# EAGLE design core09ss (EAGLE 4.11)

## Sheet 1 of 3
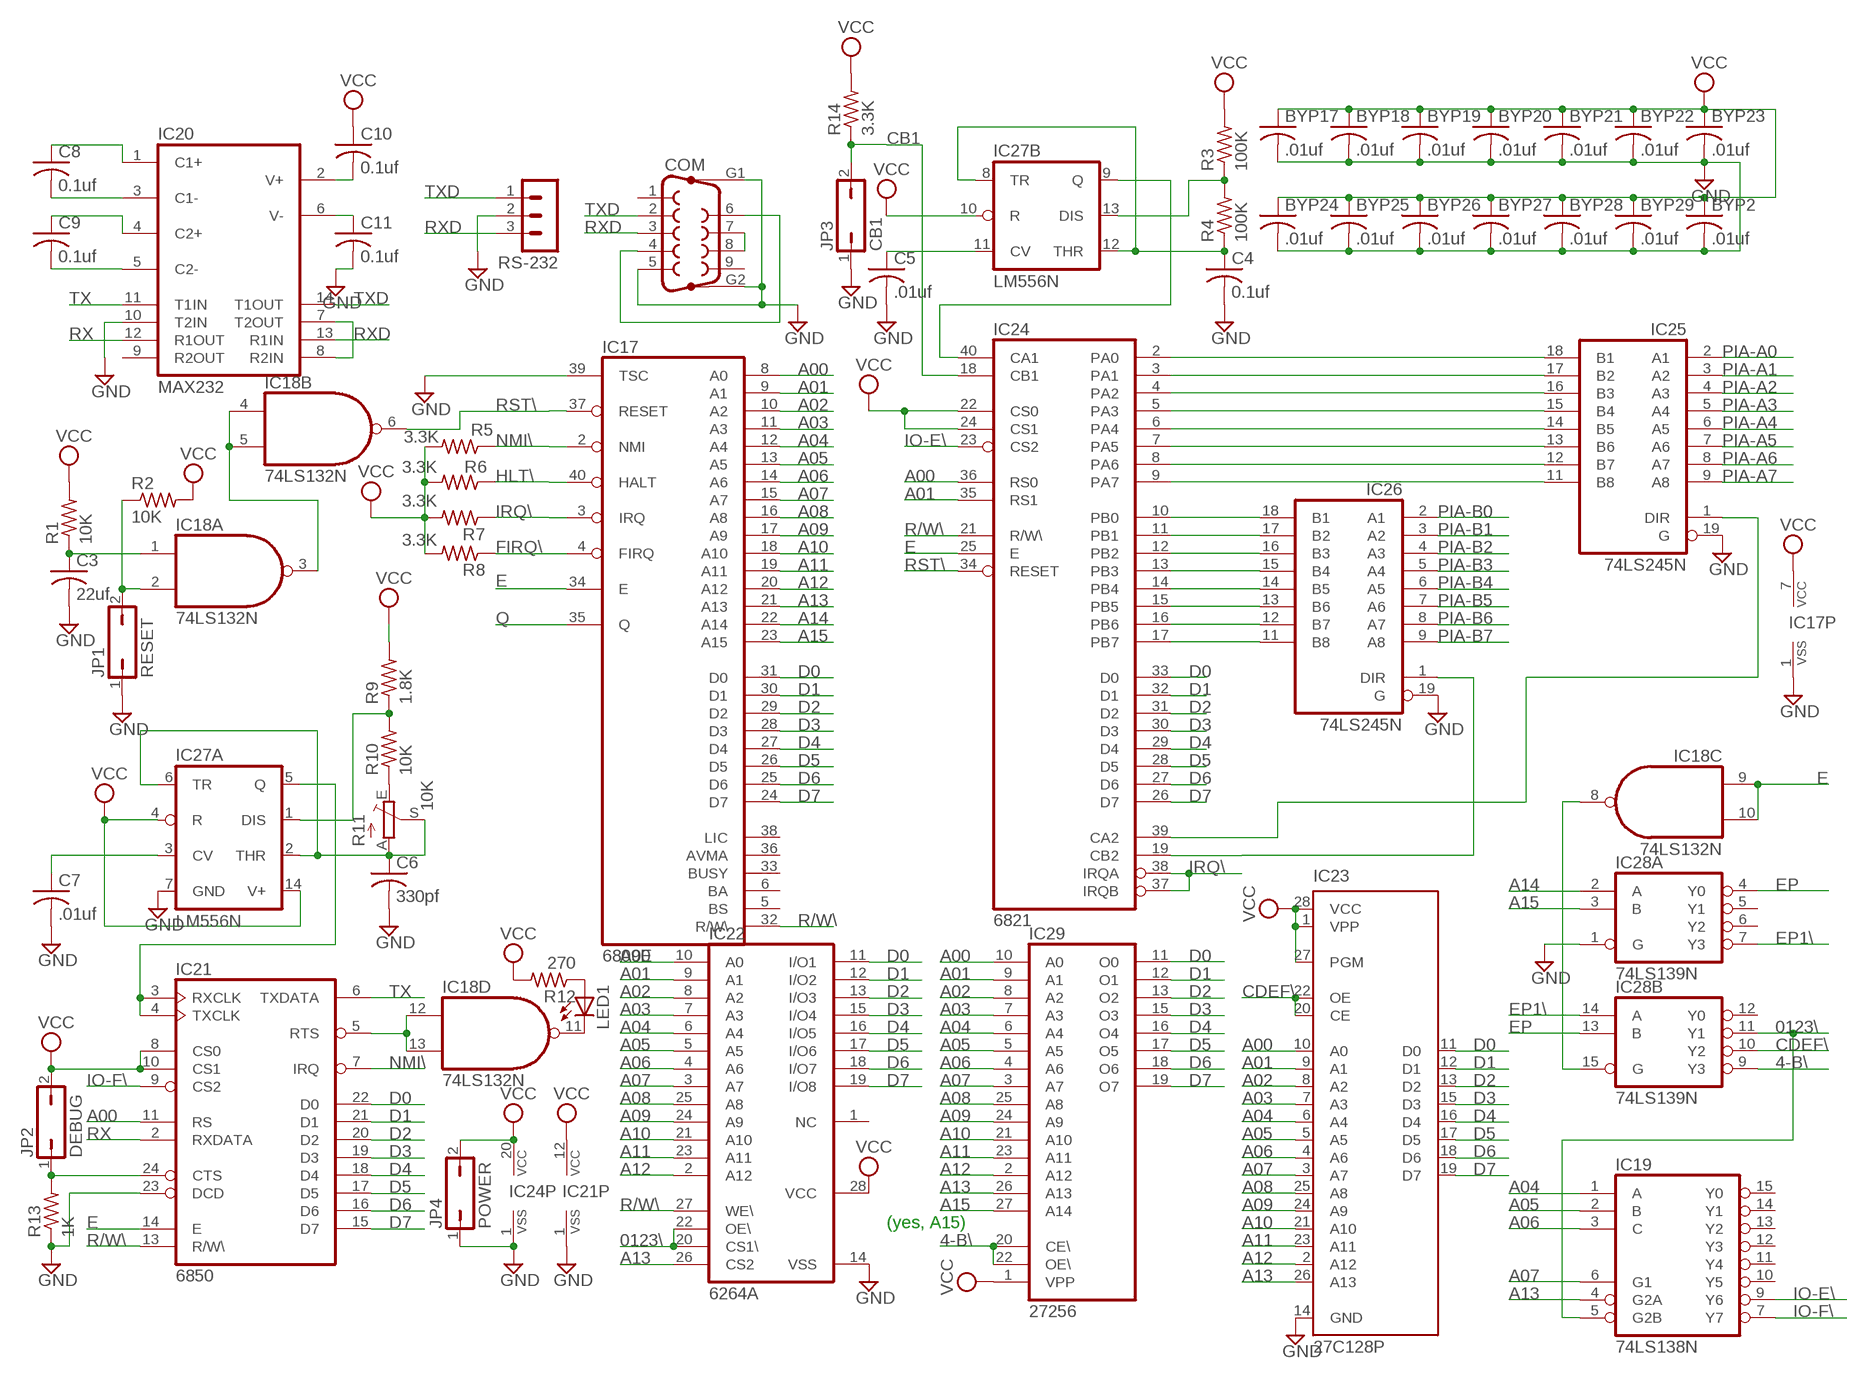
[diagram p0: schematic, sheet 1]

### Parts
BYP2  .01uf  C-US050-025X075  [C050-025X075]
BYP17  .01uf  C-US050-025X075  [C050-025X075]
BYP18  .01uf  C-US050-025X075  [C050-025X075]
BYP19  .01uf  C-US050-025X075  [C050-025X075]
BYP20  .01uf  C-US050-025X075  [C050-025X075]
BYP21  .01uf  C-US050-025X075  [C050-025X075]
BYP22  .01uf  C-US050-025X075  [C050-025X075]
BYP23  .01uf  C-US050-025X075  [C050-025X075]
BYP24  .01uf  C-US050-025X075  [C050-025X075]
BYP25  .01uf  C-US050-025X075  [C050-025X075]
BYP26  .01uf  C-US050-025X075  [C050-025X075]
BYP27  .01uf  C-US050-025X075  [C050-025X075]
BYP28  .01uf  C-US050-025X075  [C050-025X075]
BYP29  .01uf  C-US050-025X075  [C050-025X075]
C3  22uf  C-US102-043X133  [C102-043X133]
C4  0.1uf  C-US050-025X075  [C050-025X075]
C5  .01uf  C-US050-025X075  [C050-025X075]
C6  330pf  C-US050-025X075  [C050-025X075]
C7  .01uf  C-US050-025X075  [C050-025X075]
C8  0.1uf  C-US050-025X075  [C050-025X075]
C9  0.1uf  C-US050-025X075  [C050-025X075]
C10  0.1uf  C-US050-025X075  [C050-025X075]
C11  0.1uf  C-US050-025X075  [C050-025X075]
COM  F09HP  [F09HP]
IC17  6809E  [DIL40]
IC18  74LS132N  74LS00N  [DIL14]
IC19  74LS138N  [DIL16]
IC20  MAX232  [DIL16]
IC21  6850  [DIL24]
IC22  6264A  [DIL28-6]
IC23  27C128P  [DIL28-6]
IC24  6821  [DIL40]
IC25  74LS245N  [DIL20]
IC26  74LS245N  [DIL20]
IC27  LM556N  [DIL14]
IC28  74LS139N  [DIL16]
IC29  27256  [DIL28]
JP1  RESET  JP1Q  [JP1]
JP2  DEBUG  JP1Q  [JP1]
JP3  CB1  JP1Q  [JP1]
JP4  POWER  JP1Q  [JP1]
LED1  LED3MM  [LED3MM]
R1  10K  R-US_0207/7  [0207/7]
R2  10K  R-US_0207/7  [0207/7]
R3  100K  R-US_0207/7  [0207/7]
R4  100K  R-US_0207/7  [0207/7]
R5  3.3K  R-US_0207/7  [0207/7]
R6  3.3K  R-US_0207/7  [0207/7]
R7  3.3K  R-US_0207/7  [0207/7]
R8  3.3K  R-US_0207/7  [0207/7]
R9  1.8K  R-US_0207/7  [0207/7]
R10  10K  R-US_0207/7  [0207/7]
R11  10K  TRIM_EU-B90P  [SP19L]
R12  270  R-US_0207/7  [0207/7]
R13  1K  R-US_0207/7  [0207/7]
R14  3.3K  R-US_0207/7  [0207/7]
RS-232  MA03-1  [MA03-1]

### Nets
4-B\: IC28.9(B:Y3) IC29.20(CE\) IC29.22(OE\)
0123\: IC19.5(G2B) IC22.20(CS1\) IC22.22(OE\) IC28.11(B:Y1)
A00: IC17.8(A0) IC21.11(RS) IC22.10(A0) IC23.10(A0) IC24.36(RS0) IC29.10(A0)
A01: IC17.9(A1) IC22.9(A1) IC23.9(A1) IC24.35(RS1) IC29.9(A1)
A02: IC17.10(A2) IC22.8(A2) IC23.8(A2) IC29.8(A2)
A03: IC17.11(A3) IC22.7(A3) IC23.7(A3) IC29.7(A3)
A04: IC17.12(A4) IC19.1(A) IC22.6(A4) IC23.6(A4) IC29.6(A4)
A05: IC17.13(A5) IC19.2(B) IC22.5(A5) IC23.5(A5) IC29.5(A5)
A06: IC17.14(A6) IC19.3(C) IC22.4(A6) IC23.4(A6) IC29.4(A6)
A07: IC17.15(A7) IC19.6(G1) IC22.3(A7) IC23.3(A7) IC29.3(A7)
A08: IC17.16(A8) IC22.25(A8) IC23.25(A8) IC29.25(A8)
A09: IC17.17(A9) IC22.24(A9) IC23.24(A9) IC29.24(A9)
A10: IC17.18(A10) IC22.21(A10) IC23.21(A10) IC29.21(A10)
A11: IC17.19(A11) IC22.23(A11) IC23.23(A11) IC29.23(A11)
A12: IC17.20(A12) IC22.2(A12) IC23.2(A12) IC29.2(A12)
A13: IC17.21(A13) IC19.4(G2A) IC22.26(CS2) IC23.26(A13) IC29.26(A13)
A14: IC17.22(A14) IC28.2(A:A)
A15: IC17.23(A15) IC28.3(A:B) IC29.27(A14)
CB1: IC24.18(CB1) JP3.2 R14.1
CDEF\: IC23.20(CE) IC23.22(OE) IC28.10(B:Y2)
D0: IC17.31(D0) IC21.22(D0) IC22.11(I/O1) IC23.11(D0) IC24.33(D0) IC29.11(O0)
D1: IC17.30(D1) IC21.21(D1) IC22.12(I/O2) IC23.12(D1) IC24.32(D1) IC29.12(O1)
D2: IC17.29(D2) IC21.20(D2) IC22.13(I/O3) IC23.13(D2) IC24.31(D2) IC29.13(O2)
D3: IC17.28(D3) IC21.19(D3) IC22.15(I/O4) IC23.15(D3) IC24.30(D3) IC29.15(O3)
D4: IC17.27(D4) IC21.18(D4) IC22.16(I/O5) IC23.16(D4) IC24.29(D4) IC29.16(O4)
D5: IC17.26(D5) IC21.17(D5) IC22.17(I/O6) IC23.17(D5) IC24.28(D5) IC29.17(O5)
D6: IC17.25(D6) IC21.16(D6) IC22.18(I/O7) IC23.18(D6) IC24.27(D6) IC29.18(O6)
D7: IC17.24(D7) IC21.15(D7) IC22.19(I/O8) IC23.19(D7) IC24.26(D7) IC29.19(O7)
E: IC17.34(E) IC18.9(C:I0) IC18.10(C:I1) IC21.14(E) IC24.25(E) ; also sheet 3
EP: IC28.4(A:Y0) IC28.13(B:B)
EP1\: IC28.7(A:Y3) IC28.14(B:A)
FIRQ\: IC17.4(FIRQ) R8.1
GND [Power]: BYP2.2 BYP17.2 BYP18.2 BYP19.2 BYP20.2 BYP21.2 BYP22.2 BYP23.2 BYP24.2 BYP25.2 BYP26.2 BYP27.2 BYP28.2 BYP29.2 C3.2 C4.2 C5.2 C6.2 C7.2 C11.2 COM.5 COM.G1 COM.G2 IC17.1(VSS) IC17.39(TSC) IC20.10(T2IN) IC21.1(VSS) IC21.23(DCD) IC22.14(VSS) IC23.14(GND) IC24.1(VSS) IC25.19(G) IC26.19(G) IC27.7(A:GND) IC28.1(A:G) JP1.1 JP3.1 JP4.1 R13.1 RS-232.2 ; also sheet 2,3
HLT\: IC17.40(HALT) R5.1
IO-E\: IC19.9(Y6) IC24.23(CS2)
IO-F\: IC19.7(Y7) IC21.9(CS2)
IRQ\: IC17.3(IRQ) IC24.37(IRQB) IC24.38(IRQA) R7.1
N$1: COM.4 COM.6
N$5: IC24.2(PA0) IC25.18(B1)
N$6: IC18.3(A:O) IC18.4(B:I0) IC18.5(B:I1)
N$21: C3.1 IC18.1(A:I0) R1.1
N$22: IC18.2(A:I1) JP1.2 R2.1
N$23: IC21.3(RXCLK) IC21.4(TXCLK) IC27.5(A:Q)
N$24: IC24.10(PB0) IC26.18(B1)
N$25: IC24.11(PB1) IC26.17(B2)
N$27: C6.1 IC27.2(A:THR) IC27.6(A:TR) R11.A R11.S
N$28: IC27.1(A:DIS) R9.1 R10.2
N$94: IC24.12(PB2) IC26.16(B3)
N$124: IC24.13(PB3) IC26.15(B4)
N$125: IC24.14(PB4) IC26.14(B5)
N$126: IC24.15(PB5) IC26.13(B6)
N$127: IC24.16(PB6) IC26.12(B7)
N$128: IC24.17(PB7) IC26.11(B8)
N$129: IC24.3(PA1) IC25.17(B2)
N$130: IC24.4(PA2) IC25.16(B3)
N$131: IC24.5(PA3) IC25.15(B4)
N$132: IC24.6(PA4) IC25.14(B5)
N$133: IC24.7(PA5) IC25.13(B6)
N$134: IC24.8(PA6) IC25.12(B7)
N$135: IC24.9(PA7) IC25.11(B8)
N$136: IC24.19(CB2) IC26.1(DIR)
N$137: IC24.39(CA2) IC25.1(DIR)
N$138: IC24.40(CA1) IC27.9(B:Q)
N$140: C4.1 IC27.8(B:TR) IC27.12(B:THR) R4.1
N$141: IC27.13(B:DIS) R3.1 R4.2
N$142: C5.1 IC27.11(B:CV)
N$143: R10.1 R11.E
N$145: COM.7 COM.8
N$147: IC18.12(D:I0) IC18.13(D:I1) IC21.5(RTS)
N$148: IC18.11(D:O) LED1.K(C)
N$149: LED1.A R12.1
N$150: IC21.24(CTS) JP2.1 R13.2
N$151: IC18.8(C:O) IC28.15(B:G)
N$153: IC20.7(T2OUT) IC20.8(R2IN)
N$154: C7.1 IC27.3(A:CV)
N$155: C9.2 IC20.5(C2-)
N$156: C9.1 IC20.4(C2+)
N$157: C8.2 IC20.3(C1-)
N$158: C8.1 IC20.1(C1+)
N$159: C11.1 IC20.6(V-)
N$160: C10.2 IC20.2(V+)
NMI\: IC17.2(NMI) IC21.7(IRQ) R6.1
PIA-A0: IC25.2(A1) ; also sheet 2
PIA-A1: IC25.3(A2) ; also sheet 2
PIA-A2: IC25.4(A3) ; also sheet 2
PIA-A3: IC25.5(A4) ; also sheet 2
PIA-A4: IC25.6(A5) ; also sheet 2
PIA-A5: IC25.7(A6) ; also sheet 2
PIA-A6: IC25.8(A7) ; also sheet 2
PIA-A7: IC25.9(A8) ; also sheet 2
PIA-B0: IC26.2(A1) ; also sheet 2
PIA-B1: IC26.3(A2) ; also sheet 2
PIA-B2: IC26.4(A3) ; also sheet 2
PIA-B3: IC26.5(A4) ; also sheet 2
PIA-B4: IC26.6(A5) ; also sheet 2
PIA-B5: IC26.7(A6) ; also sheet 2
PIA-B6: IC26.8(A7) ; also sheet 2
PIA-B7: IC26.9(A8) ; also sheet 2
Q: IC17.35(Q) ; also sheet 3
R/W\: IC17.32(R/W\) IC21.13(R/W\) IC22.27(WE\) IC24.21(R/W\)
RST\: IC17.37(RESET) IC18.6(B:O) IC24.34(RESET)
RX: IC20.12(R1OUT) IC21.2(RXDATA)
RXD: COM.3 IC20.13(R1IN) RS-232.3
TX: IC20.11(T1IN) IC21.6(TXDATA)
TXD: COM.2 IC20.14(T1OUT) RS-232.1
VCC [Power]: BYP2.1 BYP17.1 BYP18.1 BYP19.1 BYP20.1 BYP21.1 BYP22.1 BYP23.1 BYP24.1 BYP25.1 BYP26.1 BYP27.1 BYP28.1 BYP29.1 C10.1 IC17.7(VCC) IC21.8(CS0) IC21.10(CS1) IC21.12(VCC) IC22.28(VCC) IC23.1(VPP) IC23.27(PGM) IC23.28(VCC) IC24.20(VCC) IC24.22(CS0) IC24.24(CS1) IC27.4(A:R) IC27.10(B:R) IC27.14(A:V+) IC29.1(VPP) JP2.2 JP4.2 R1.2 R2.2 R3.2 R5.2 R6.2 R7.2 R8.2 R9.2 R12.2 R14.2 ; also sheet 2,3
Unconnected: COM.1 COM.9 IC17.5(BS) IC17.6(BA) IC17.33(BUSY) IC17.36(AVMA) IC17.38(LIC) IC19.10(Y5) IC19.11(Y4) IC19.12(Y3) IC19.13(Y2) IC19.14(Y1) IC19.15(Y0) IC20.9(R2OUT) IC22.1(NC) IC28.5(A:Y1) IC28.6(A:Y2) IC28.12(B:Y0)

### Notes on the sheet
- (yes, A15)

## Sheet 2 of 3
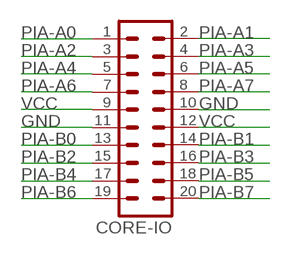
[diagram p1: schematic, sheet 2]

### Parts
CORE-IO  MA10-2  [MA10-2]

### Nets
GND [Power]: CORE-IO.10 CORE-IO.11 ; also sheet 1,3
PIA-A0: CORE-IO.1 ; also sheet 1
PIA-A1: CORE-IO.2 ; also sheet 1
PIA-A2: CORE-IO.3 ; also sheet 1
PIA-A3: CORE-IO.4 ; also sheet 1
PIA-A4: CORE-IO.5 ; also sheet 1
PIA-A5: CORE-IO.6 ; also sheet 1
PIA-A6: CORE-IO.7 ; also sheet 1
PIA-A7: CORE-IO.8 ; also sheet 1
PIA-B0: CORE-IO.13 ; also sheet 1
PIA-B1: CORE-IO.14 ; also sheet 1
PIA-B2: CORE-IO.15 ; also sheet 1
PIA-B3: CORE-IO.16 ; also sheet 1
PIA-B4: CORE-IO.17 ; also sheet 1
PIA-B5: CORE-IO.18 ; also sheet 1
PIA-B6: CORE-IO.19 ; also sheet 1
PIA-B7: CORE-IO.20 ; also sheet 1
VCC [Power]: CORE-IO.9 CORE-IO.12 ; also sheet 1,3

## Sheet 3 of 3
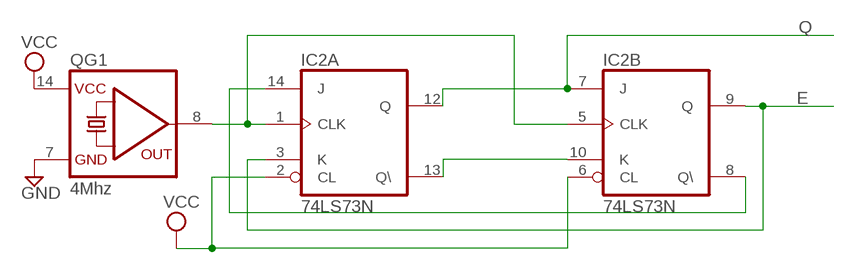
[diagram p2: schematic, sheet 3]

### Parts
IC2  74LS73N  [DIL14]
QG1  4Mhz  QG5860  [DIL14S]

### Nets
E: IC2.3(A:K) IC2.9(B:Q) ; also sheet 1
GND [Power]: QG1.7(GND) ; also sheet 1,2
N$2: IC2.1(A:CLK) IC2.5(B:CLK) QG1.8(OUT)
N$3: IC2.10(B:K) IC2.13(A:Q\)
N$7: IC2.8(B:Q\) IC2.14(A:J)
Q: IC2.7(B:J) IC2.12(A:Q) ; also sheet 1
VCC [Power]: IC2.2(A:CL) IC2.6(B:CL) QG1.14(VCC) ; also sheet 1,2

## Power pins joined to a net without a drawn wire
GND: IC2.11(P:GND) IC18.7(P:GND) IC19.8(GND) IC20.15(GND) IC25.10(GND) IC26.10(GND) IC28.8(P:GND) IC29.14(GND)
VCC: IC2.4(P:VCC) IC18.14(P:VCC) IC19.16(VCC) IC20.16(VCC) IC25.20(VCC) IC26.20(VCC) IC28.16(P:VCC) IC29.28(VCC)

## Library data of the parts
BYP2 BYP17-BYP29 C3-C11 = rcl:C-US: CAPACITOR, American symbol
COM = con-subd:F09HP: SUB-D
CORE-IO = con-lstb:MA10-2: PIN HEADER
IC2 = 74xx-us:74*73: Dual J-K FLIP FLOP, clear
IC17 = micro-motorola:6809E: MICROCONTROLLER/MEMORY DEVICE
IC18 = 74xx-us:74*00: Quad 2-input NAND gate
IC19 = 74xx-us:74*138: 3-line to 8-line DECODER/DEMULTIPLEXER
IC20 = maxim:MAX232: RS232 TRANSEIVER
IC21 = micro-motorola:6850: MICROCONTROLLER/MEMORY DEVICE
IC22 = memory-hitachi:6264A: MEMORY
IC23 = microchip:27*128: CMOS EPROM 128 K (16 K x 8)
IC24 = micro-motorola:6821: MICROCONTROLLER/MEMORY DEVICE
IC25 IC26 = 74xx-us:74*245: Octal BUS TRANSCEIVER, 3-state
IC27 = linear:*556: Dual TIMER
IC28 = 74xx-us:74*139: Dual 2-line to 4-line DECODER/DEMULTIPLEXER
IC29 = memory:27256: MEMORY
JP1-JP4 = jumper:JP1Q: JUMPER
LED1 = led:LED: LED
QG1 = crystal:QG5860: CRYSTAL RESONATOR
R1-R10 R12-R14 = rcl:R-US_: RESISTOR, American symbol
R11 = pot:TRIM_EU-: POTENTIOMETER
RS-232 = con-lstb:MA03-1: PIN HEADER

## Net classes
1 Power: width 0.508 mm, drill 0.254 mm, clearance 0.254 mm

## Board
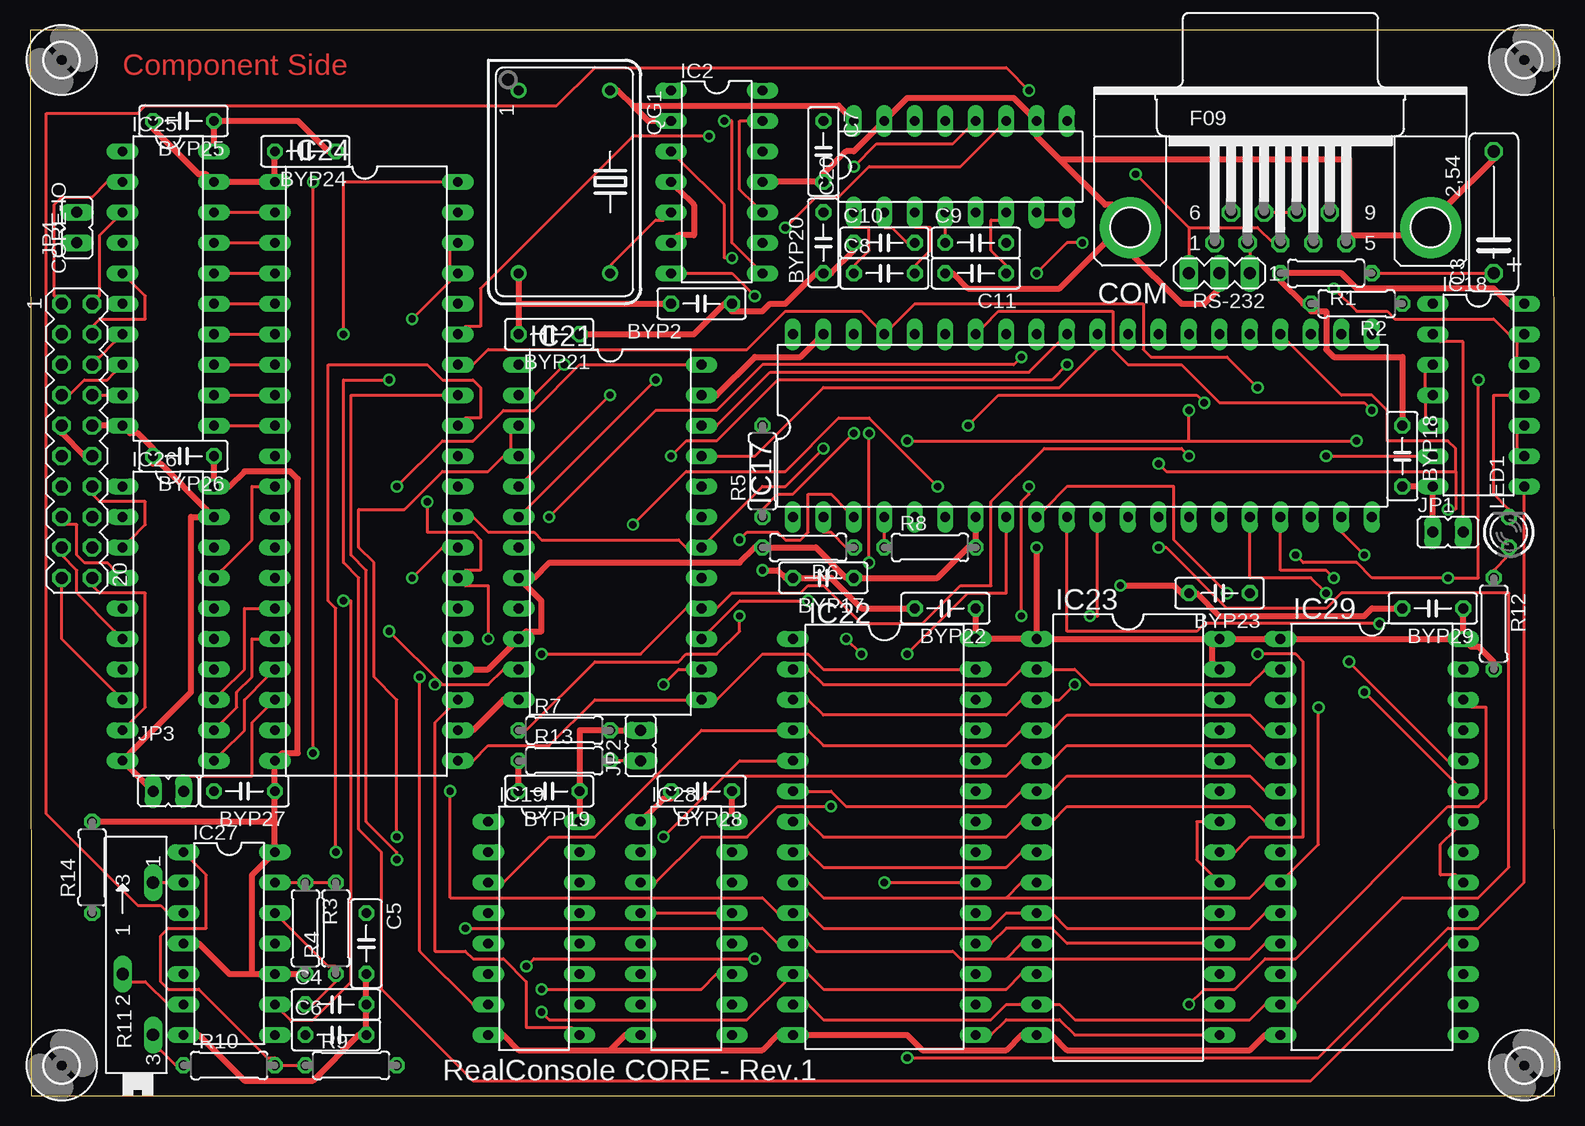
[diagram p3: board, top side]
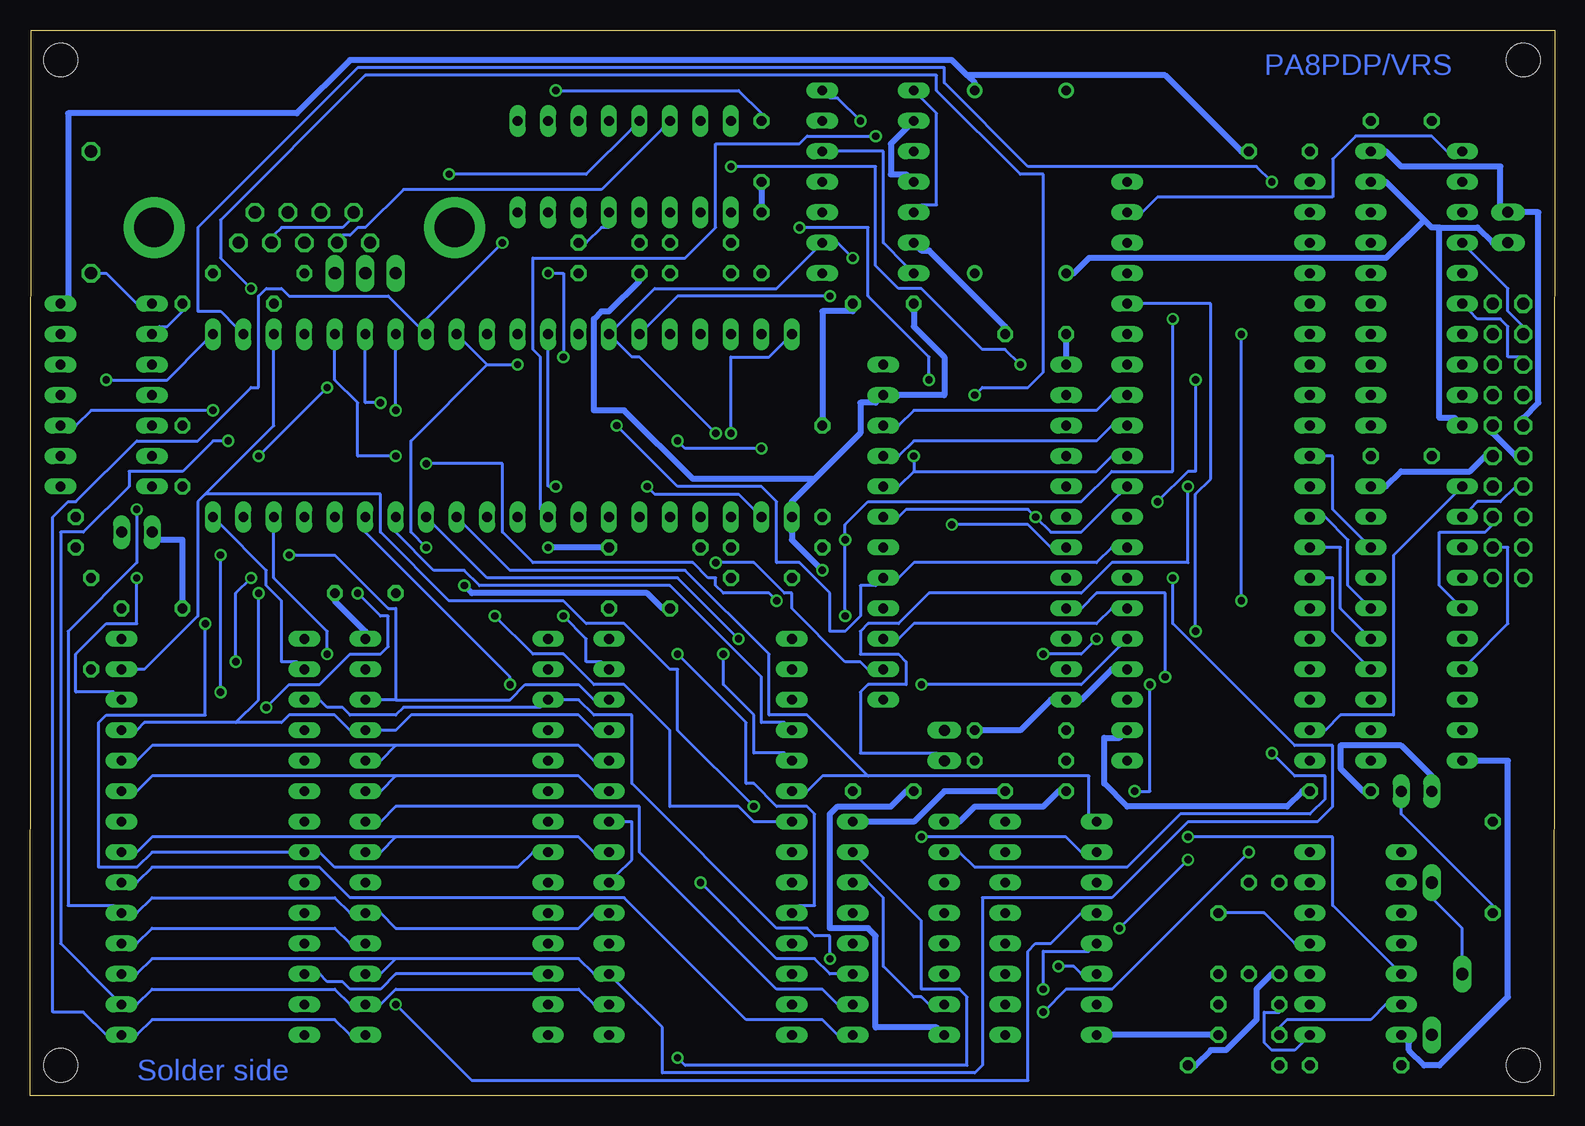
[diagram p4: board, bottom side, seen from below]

Size 127.11 x 88.87 mm. Coordinates in mm from the lower left corner, seen from the top.
Outline: 0.1,0 127.11,0 127.01,88.87 0,88.87 0.1,0
Copper layers (1*16): Top 0.035mm / dielectric 1.5mm / Bottom 0.035mm
Design rules "olimex10mil": minimum track width 10mil, minimum drill 24mil, track to track 10mil, track to pad 10mil, pad to pad 10mil, via to via 10mil, smd to smd 10mil, copper to edge 40mil, drill to drill 10mil, minimum pad ring 10mil, minimum via ring 8mil, stop-mask expansion 0mil, vias tented up to drill 0mil, thermal gap 10mil

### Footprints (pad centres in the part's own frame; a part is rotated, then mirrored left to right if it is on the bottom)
C050-025X075 = drill 0.813 octagon: 1 -2.54,0; 2 2.54,0
C102-043X133 = drill 1.016 octagon: 1 -5.08,0; 2 5.08,0
F09HP = drill 1.016 octagon: 1 -5.486,-1.27; 2 -2.743,-1.27; 3 0,-1.27; 4 2.743,-1.27; 5 5.486,-1.27; 6 -4.115,1.27; 7 -1.372,1.27; 8 1.372,1.27; 9 4.115,1.27 | drill 3.302 pad 5.08 round: G1 -12.522,0; G2 12.522,0
MA10-2 = drill 1.016 octagon: 1 -11.43,-1.27; 2 -11.43,1.27; 3 -8.89,-1.27; 4 -8.89,1.27; 5 -6.35,-1.27; 6 -6.35,1.27; 7 -3.81,-1.27; 8 -3.81,1.27; 9 -1.27,-1.27; 10 -1.27,1.27; 11 1.27,-1.27; 12 1.27,1.27; 13 3.81,-1.27; 14 3.81,1.27; 15 6.35,-1.27; 16 6.35,1.27; 17 8.89,-1.27; 18 8.89,1.27; 19 11.43,-1.27; 20 11.43,1.27
DIL14 = drill 0.813 long: 1 -7.62,-3.81; 2 -5.08,-3.81; 3 -2.54,-3.81; 4 0,-3.81; 5 2.54,-3.81; 6 5.08,-3.81; 7 7.62,-3.81; 8 7.62,3.81; 9 5.08,3.81; 10 2.54,3.81; 11 0,3.81; 12 -2.54,3.81; 13 -5.08,3.81; 14 -7.62,3.81
DIL40 = drill 0.813 long: 1 -24.13,-7.62; 2 -21.59,-7.62; 3 -19.05,-7.62; 4 -16.51,-7.62; 5 -13.97,-7.62; 6 -11.43,-7.62; 7 -8.89,-7.62; 8 -6.35,-7.62; 9 -3.81,-7.62; 10 -1.27,-7.62; 11 1.27,-7.62; 12 3.81,-7.62; 13 6.35,-7.62; 14 8.89,-7.62; 15 11.43,-7.62; 16 13.97,-7.62; 17 16.51,-7.62; 18 19.05,-7.62; 19 21.59,-7.62; 20 24.13,-7.62; 21 24.13,7.62; 22 21.59,7.62; 23 19.05,7.62; 24 16.51,7.62; 25 13.97,7.62; 26 11.43,7.62; 27 8.89,7.62; 28 6.35,7.62; 29 3.81,7.62; 30 1.27,7.62; 31 -1.27,7.62; 32 -3.81,7.62; 33 -6.35,7.62; 34 -8.89,7.62; 35 -11.43,7.62; 36 -13.97,7.62; 37 -16.51,7.62; 38 -19.05,7.62; 39 -21.59,7.62; 40 -24.13,7.62
DIL16 = drill 0.813 long: 1 -8.89,-3.81; 2 -6.35,-3.81; 3 -3.81,-3.81; 4 -1.27,-3.81; 5 1.27,-3.81; 6 3.81,-3.81; 7 6.35,-3.81; 8 8.89,-3.81; 9 8.89,3.81; 10 6.35,3.81; 11 3.81,3.81; 12 1.27,3.81; 13 -1.27,3.81; 14 -3.81,3.81; 15 -6.35,3.81; 16 -8.89,3.81
DIL24 = drill 0.813 long: 1 -13.97,-7.62; 2 -11.43,-7.62; 3 -8.89,-7.62; 4 -6.35,-7.62; 5 -3.81,-7.62; 6 -1.27,-7.62; 7 1.27,-7.62; 8 3.81,-7.62; 9 6.35,-7.62; 10 8.89,-7.62; 11 11.43,-7.62; 12 13.97,-7.62; 13 13.97,7.62; 14 11.43,7.62; 15 8.89,7.62; 16 6.35,7.62; 17 3.81,7.62; 18 1.27,7.62; 19 -1.27,7.62; 20 -3.81,7.62; 21 -6.35,7.62; 22 -8.89,7.62; 23 -11.43,7.62; 24 -13.97,7.62
DIL28-6 = drill 0.813 long: 1 -16.51,-7.62; 2 -13.97,-7.62; 3 -11.43,-7.62; 4 -8.89,-7.62; 5 -6.35,-7.62; 6 -3.81,-7.62; 7 -1.27,-7.62; 8 1.27,-7.62; 9 3.81,-7.62; 10 6.35,-7.62; 11 8.89,-7.62; 12 11.43,-7.62; 13 13.97,-7.62; 14 16.51,-7.62; 15 16.51,7.62; 16 13.97,7.62; 17 11.43,7.62; 18 8.89,7.62; 19 6.35,7.62; 20 3.81,7.62; 21 1.27,7.62; 22 -1.27,7.62; 23 -3.81,7.62; 24 -6.35,7.62; 25 -8.89,7.62; 26 -11.43,7.62; 27 -13.97,7.62; 28 -16.51,7.62
DIL20 = drill 0.813 long: 1 -11.43,-3.81; 2 -8.89,-3.81; 3 -6.35,-3.81; 4 -3.81,-3.81; 5 -1.27,-3.81; 6 1.27,-3.81; 7 3.81,-3.81; 8 6.35,-3.81; 9 8.89,-3.81; 10 11.43,-3.81; 11 11.43,3.81; 12 8.89,3.81; 13 6.35,3.81; 14 3.81,3.81; 15 1.27,3.81; 16 -1.27,3.81; 17 -3.81,3.81; 18 -6.35,3.81; 19 -8.89,3.81; 20 -11.43,3.81
DIL28 = drill 0.813 long: 1 -16.51,-7.62; 2 -13.97,-7.62; 3 -11.43,-7.62; 4 -8.89,-7.62; 5 -6.35,-7.62; 6 -3.81,-7.62; 7 -1.27,-7.62; 8 1.27,-7.62; 9 3.81,-7.62; 10 6.35,-7.62; 11 8.89,-7.62; 12 11.43,-7.62; 13 13.97,-7.62; 14 16.51,-7.62; 15 16.51,7.62; 16 13.97,7.62; 17 11.43,7.62; 18 8.89,7.62; 19 6.35,7.62; 20 3.81,7.62; 21 1.27,7.62; 22 -1.27,7.62; 23 -3.81,7.62; 24 -6.35,7.62; 25 -8.89,7.62; 26 -11.43,7.62; 27 -13.97,7.62; 28 -16.51,7.62
JP1 = drill 0.914 long: 1 0,-1.27; 2 0,1.27
LED3MM = drill 0.813 octagon: A -1.27,0; K 1.27,0
DIL14S = drill 0.813 round: 1 -7.62,-3.81; 7 7.62,-3.81; 8 7.62,3.81; 14 -7.62,3.81
0207/7 = drill 0.813 octagon: 1 -3.81,0; 2 3.81,0
SP19L = drill 1.016 long: A 5.715,-1.27; E -6.985,-1.27; S -1.905,1.27
MA03-1 = drill 1.016 long: 1 -2.54,0; 2 0,0; 3 2.54,0
2,8 = hole 2.8: 0,0

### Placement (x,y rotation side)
BYP2  55.98,66.05 180 top
BYP17  66.14,43.19 180 top
BYP18  114.4,53.35 270 top
BYP19  43.28,25.41 180 top
BYP20  66.14,71.13 90 top
BYP21  43.28,63.51 180 top
BYP22  76.3,40.65 180 top
BYP23  99.16,41.92 180 top
BYP24  22.96,78.75 180 top
BYP25  12.8,81.29 180 top
BYP26  12.8,53.35 180 top
BYP27  17.88,25.41 180 top
BYP28  55.98,25.41 180 top
BYP29  116.94,40.65 180 top
C3  122.02,73.67 90 top
C4  25.5,7.63 0 top
C5  28.04,12.71 270 top
C6  25.5,5.09 0 top
C7  66.14,78.75 270 top
C8  71.22,68.59 0 top
C9  78.84,71.13 0 top
C10  71.22,71.13 0 top
C11  78.84,68.59 180 top
COM  104.24,72.4 0 top
CORE-IO  3.91,54.62 270 top
IC2  57.25,76.21 270 top
IC17  87.73,55.89 0 top
IC18  120.75,58.43 270 top
IC19  42.01,13.98 270 top
IC20  77.57,77.48 0 top
IC21  48.36,47 270 top
IC22  71.22,21.6 270 top
IC23  91.54,21.6 270 top
IC24  28.04,52.08 270 top
IC25  11.53,67.32 270 top
IC26  11.53,39.38 270 top
IC27  16.61,12.71 270 top
IC28  54.71,13.98 270 top
IC29  111.86,21.6 270 top
JP1  118.21,47 270 top
JP2  50.9,29.22 0 top
JP3  11.53,25.41 270 top
JP4  3.91,72.4 0 top
LED1  123.29,47 90 top
QG1  44.55,76.21 270 top
R1  108.05,68.59 180 top
R2  110.59,66.05 180 top
R3  22.96,13.98 270 top
R4  25.5,13.98 90 top
R5  61.06,52.08 90 top
R6  64.87,45.73 180 top
R7  44.55,30.49 0 top
R8  75.03,45.73 0 top
R9  26.77,2.55 0 top
R10  16.61,2.55 0 top
R11  8.99,12.08 90 top
R12  122.02,39.38 270 top
R13  44.55,27.95 0 top
R14  5.18,19.06 90 top
RS-232  99.16,68.59 180 top
U$3  [2,8]  2.64,86.37 0 top
U$4  [2,8]  2.64,2.55 0 top
U$5  [2,8]  124.56,86.37 0 top
U$6  [2,8]  124.56,2.55 0 top

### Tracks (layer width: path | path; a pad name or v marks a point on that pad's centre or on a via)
4-B\
  Top 0.254: IC29.22 118.84,22.24 117.57,20.97 117.57,18.43 118.84,18.43 IC29.20
  Bottom 0.254: IC28.9 59.79,5.09 61.06,6.36 67.41,6.36 77.57,16.52 100.43,16.52 102.97,19.06 116.94,19.06 118.21,17.79 IC29.20
0123\  (via drill 0.61)
  Top 0.254: v42.64,8.9 55.98,8.9 57.25,10.17 IC28.11 | v71.22,17.79 77.57,17.79 IC22.20
  Bottom 0.254: IC22.20 78.2,18.43 76.93,19.7 76.93,22.87 77.57,22.87 IC22.22 | v42.64,8.9 42.64,12.08 38.83,12.08 IC19.5 | v71.22,17.79 64.87,11.44 61.69,11.44 60.42,10.17 59.79,10.17 IC28.11
A00  (via drill 0.61)
  Top 0.254: 34.39,34.3 38.2,34.3 39.47,35.57 IC21.11 | 34.39,34.3 v29.94,38.75 | v73.12,36.84 78.2,41.92 81.38,41.92 81.38,47 IC17.8 | IC29.10 102.97,15.25 101.7,13.98 86.46,13.98 85.19,15.25 IC23.10 82.65,15.25 81.38,15.25 80.11,13.98 66.14,13.98 64.87,15.25 IC22.10 62.33,15.25 61.06,16.52 35.02,16.52 v35.02,25.41 | v33.75,34.3 34.39,34.3
  Bottom 0.254: v29.94,38.75 29.94,50.18 28.67,51.45 28.67,66.05 34.39,66.05 IC24.36 | v73.12,36.84 67.41,31.13 67.41,26.05 66.77,26.05 64.87,24.14 62.33,24.14 61.69,23.51 61.69,15.89 62.96,15.89 IC22.10 | v33.75,34.3 33.75,25.41 v35.02,25.41
A01  (via drill 0.61)
  Top 0.254: 81.38,16.52 66.14,16.52 64.87,17.79 IC22.9 | 81.38,16.52 82.65,17.79 IC23.9 | 81.38,16.52 101.7,16.52 102.97,17.79 IC29.9 104.87,18.43 107.41,20.97 v107.41,32.4 | v56.61,80.02 50.26,80.02 37.56,67.32 37.56,64.15 36.29,64.15 IC24.35 | v99.79,41.92 95.35,46.37 95.35,50.81 86.46,50.81 84.55,48.91 IC17.9
  Bottom 0.254: v56.61,80.02 62.33,80.02 62.96,79.39 69.95,79.39 69.95,72.4 72.49,69.86 85.19,69.86 85.19,62.24 84.55,61.61 84.55,48.91 IC17.9 | v107.41,32.4 105.51,34.3 102.97,34.3 100.43,36.84 97.89,36.84 97.25,37.48 97.25,40.02 97.89,40.02 v99.79,41.92
A02  (via drill 0.61)
  Top 0.254: IC22.8 64.87,20.33 66.14,19.06 81.38,19.06 82.65,20.33 IC23.8 | v112.49,39.38 97.89,39.38 97.25,38.75 86.46,38.75 86.46,47 IC17.10
  Bottom 0.254: IC23.8 85.19,20.33 86.46,19.06 101.7,19.06 102.97,20.33 IC29.8 105.51,20.33 116.94,20.33 118.21,19.06 121.38,19.06 121.38,31.13 120.75,31.76 112.49,31.76 v112.49,39.38
A03  (via drill 0.61)
  Top 0.254: IC22.7 64.87,22.87 66.14,21.6 81.38,21.6 82.65,22.87 IC23.7 85.19,22.87 86.46,24.14 101.7,24.14 102.97,22.87 IC29.7 | v88.36,40.02 89,40.02 89,47 IC17.11
  Bottom 0.254: v88.36,40.02 85.19,36.84 82.65,36.84 80.11,34.3 77.57,34.3 73.76,30.49 73.76,24.14 68.04,24.14 66.77,22.87 64.87,22.87 IC22.7
A04
  Top 0.254: IC29.6 102.97,25.41 101.7,26.68 86.46,26.68 85.19,25.41 IC23.6 82.65,25.41 81.38,24.14 68.04,24.14 66.77,25.41 64.87,25.41 IC22.6
  Bottom 0.254: 57.25,26.68 61.06,26.68 62.33,25.41 IC22.6 | 57.25,26.68 38.83,26.68 38.83,23.51 IC19.1 | 57.25,26.68 62.33,31.76 65.5,31.76 65.5,36.84 72.49,43.83 87.09,43.83 90.9,47.64 IC17.12
A05  (via drill 0.61)
  Top 0.254: 57.88,26.68 59.15,27.95 62.33,27.95 IC22.5 | v52.8,21.6 57.88,26.68 | 57.88,26.68 81.38,26.68 82.65,27.95 IC23.5 85.19,27.95 86.46,29.22 101.7,29.22 102.97,27.95 IC29.5 | v69.31,36.84 v68.04,38.11
  Bottom 0.254: v52.8,21.6 40.74,21.6 39.47,20.33 IC19.2 | v68.04,38.11 73.12,43.19 89,43.19 93.44,47.64 IC17.13 | v69.31,36.84 69.31,34.3 66.77,31.76 66.77,28.59 64.23,28.59 IC22.5
A06
  Top 0.254: IC19.3 39.47,17.79 43.28,21.6 47.09,21.6 55.98,30.49 62.33,30.49 IC22.4 64.87,30.49 66.14,29.22 81.38,29.22 82.65,30.49 IC23.4 85.19,30.49 86.46,31.76 101.7,31.76 102.97,30.49 IC29.4
  Bottom 0.254: IC17.14 96.62,47 93.44,43.83 90.9,43.83 89.63,42.56 73.76,42.56 66.14,34.94 66.14,31.13 64.23,31.13 IC22.4
A07  (via drill 0.61)
  Top 0.254: v41.37,10.81 42.01,11.44 v60.42,11.44 | IC22.3 64.87,33.03 66.14,31.76 81.38,31.76 82.65,33.03 IC23.3 85.19,33.03 85.82,33.03 v87.09,34.3
  Bottom 0.254: v41.37,10.81 40.1,10.81 39.47,10.17 IC19.6 | v60.42,11.44 60.42,13.35 61.69,13.35 62.33,13.98 64.87,13.98 76.93,26.05 76.93,31.76 80.11,31.76 81.38,33.03 82.65,33.03 IC23.3 84.55,32.4 95.98,32.4 96.62,31.76 100.43,31.76 101.06,32.4 102.33,32.4 102.97,33.03 IC29.3 | v87.09,34.3 87.09,34.94 99.16,47 IC17.15
A08  (via drill 0.61)
  Top 0.254: v108.05,41.92 106.78,43.19 101.7,43.19 101.7,47 IC17.16
  Bottom 0.254: IC22.25 80.11,30.49 81.38,31.76 95.35,31.76 96.62,30.49 97.89,30.49 IC23.25 100.43,30.49 101.7,31.76 105.51,31.76 106.14,31.13 109.95,31.13 | 109.95,31.13 117.57,31.13 118.21,30.49 IC29.25 | v108.05,41.92 108.05,33.03 109.95,31.13
A09  (via drill 0.61)
  Top 0.254: v108.68,43.19 108.05,43.83 104.24,43.83 104.24,47 IC17.17 | v109.95,36.21 118.21,27.95 IC29.24
  Bottom 0.254: 96.62,29.22 81.38,29.22 80.11,27.95 IC22.24 | 96.62,29.22 97.89,27.95 IC23.24 | 96.62,29.22 116.94,29.22 118.21,27.95 IC29.24 | v108.68,43.19 109.95,41.92 v109.95,36.21
A10  (via drill 0.61)
  Top 0.254: v102.33,36.84 105.51,36.84 106.14,36.21 106.14,21.6 101.7,21.6 100.43,20.33 IC23.21
  Bottom 0.254: 96.62,21.6 81.38,21.6 80.11,20.33 IC22.21 | 96.62,21.6 97.89,20.33 IC23.21 | 96.62,21.6 116.94,21.6 118.21,20.33 IC29.21 | v102.33,36.84 102.33,38.75 106.78,43.19 106.78,47 IC17.18
A11  (via drill 0.61)
  Top 0.254: v111.22,45.1 109.32,47 IC17.19 | v111.22,33.67 118.84,26.05 IC29.23
  Bottom 0.254: 96.62,26.68 81.38,26.68 80.11,25.41 IC22.23 | 96.62,26.68 97.89,25.41 IC23.23 | 96.62,26.68 116.94,26.68 118.21,25.41 IC29.23 | v111.22,33.67 v111.22,45.1
A12
  Top 0.254: IC22.2 64.87,35.57 66.14,34.3 81.38,34.3 82.65,35.57 IC23.2 85.19,35.57 87.09,35.57 88.36,34.3 101.7,34.3 102.97,35.57 IC29.2
  Bottom 0.254: IC17.20 111.22,47.64 107.41,43.83 107.41,42.56 106.14,41.29 106.14,36.21 104.87,36.21 IC29.2
A13  (via drill 0.61)
  Top 0.254: v96.62,7.63 97.89,8.9 100.43,8.9 102.97,11.44 105.51,11.44 118.21,24.14 120.75,24.14 121.38,24.78 121.38,32.4 120.11,32.4 IC29.26 | v120.75,59.7 120.75,43.19 v118.21,43.19 111.86,43.19 110.59,44.46 106.14,44.46 v105.51,45.1
  Bottom 0.254: 96.62,33.03 97.89,33.03 IC23.26 | 96.62,33.03 87.09,33.03 85.82,34.3 81.38,34.3 80.11,33.03 IC22.26 | v96.62,7.63 90.27,1.28 43.91,1.28 43.91,12.08 43.28,12.71 42.01,12.71 39.47,15.25 IC19.4 | v120.75,59.7 115.67,59.7 112.49,62.88 IC17.21 | v118.21,43.19 118.21,39.38 120.75,39.38 123.29,36.84 123.29,33.67 120.11,33.67 IC29.26 | 96.62,33.03 96.62,40.65 97.25,40.65 101.7,45.1 v105.51,45.1
A14  (via drill 0.61)
  Top 0.254: v23.59,28.59 v23.59,76.21
  Bottom 0.254: v23.59,28.59 21.69,26.68 19.15,26.68 19.15,24.78 20.42,23.51 31.21,23.51 35.66,19.06 48.36,19.06 49.63,20.33 IC28.2 | v23.59,76.21 24.86,77.48 43.91,77.48 50.9,84.47 50.9,85.74 99.79,85.74 113.13,72.4 113.13,65.42 111.22,65.42 109.95,64.15 IC17.22
A15  (via drill 0.61)
  Top 0.254: v66.77,24.14 62.33,24.14 59.79,21.6 55.98,21.6 52.17,17.79 IC28.3
  Bottom 0.254: v66.77,24.14 73.12,30.49 73.12,35.57 73.76,35.57 77.57,39.38 80.74,39.38 82.65,41.29 92.17,41.29 97.89,47 97.89,50.18 112.49,50.18 | 112.49,50.18 113.13,49.54 113.13,40.02 117.57,35.57 118.21,35.57 IC29.27 | 112.49,50.18 106.78,55.89 106.78,62.24 IC17.23
CB1
  Top 0.254: IC24.18 19.78,32.4 18.51,31.13 18.51,26.68 12.8,26.68 JP3.2
  Bottom 0.254: R14.1 5.18,15.89 12.8,23.51 12.8,24.14 JP3.2
CDEF\
  Top 0.254: IC23.20 98.52,18.43 97.25,19.7 97.25,22.87 97.89,22.87 IC23.22
  Bottom 0.254: IC28.10 59.79,7.63 61.06,8.9 64.87,8.9 76.3,20.33 76.3,24.14 96.62,24.14 97.89,22.87 IC23.22
D0  (via drill 0.61)
  Top 0.254: 81.38,11.44 77.57,11.44 76.93,12.08 65.5,12.08 64.87,12.71 IC22.11 62.33,12.71 61.06,13.98 v36.29,13.98 | 81.38,11.44 82.65,12.71 IC23.11 | 81.38,11.44 101.7,11.44 102.97,12.71 IC29.11 | IC17.31 85.82,62.88 83.28,60.34 61.69,60.34 57.25,55.89 IC21.22 | v30.58,19.7 30.58,20.33 28.04,22.87 28.04,43.83 26.77,45.1 26.77,58.43 34.39,58.43 IC24.33
  Bottom 0.254: IC24.33 36.93,58.43 38.2,57.16 53.44,57.16 54.71,55.89 IC21.22 | v30.58,19.7 v36.29,13.98
D1  (via drill 0.61)
  Top 0.254: IC23.12 82.65,10.17 81.38,8.9 66.14,8.9 64.87,10.17 IC22.12 62.96,9.54 59.79,6.36 43.28,6.36 v42.64,7 | IC17.30 89,62.24 85.82,59.07 66.14,59.07 60.42,53.35 57.25,53.35 IC21.21 | v25.5,20.33 25.5,40.65 24.86,41.29 24.86,60.97 33.12,60.97 34.39,59.7 36.93,59.7 37.56,59.07 37.56,56.53 36.29,56.53 IC24.32
  Bottom 0.254: IC29.12 102.97,10.17 102.33,9.54 101.06,9.54 100.43,8.9 97.89,8.9 96.62,10.17 85.19,10.17 IC23.12 | IC24.32 36.93,55.89 38.2,54.62 53.44,54.62 54.71,53.35 IC21.21 | v42.64,7 40.74,8.9 36.93,8.9 v25.5,20.33
D2  (via drill 0.61)
  Top 0.254: IC22.13 64.87,7.63 66.14,6.36 80.11,6.36 81.38,7.63 82.65,7.63 IC23.13 85.19,7.63 85.82,7.63 87.09,6.36 101.7,6.36 102.97,7.63 IC29.13 105.51,7.63 114.4,16.52 120.75,16.52 123.29,19.06 123.29,41.92 109.32,41.92 108.05,40.65 99.79,40.65 94.71,45.73 v94.08,45.73 | v86.46,60.97 85.19,59.7 62.33,59.7 57.25,54.62 54.71,54.62 v53.44,53.35
  Bottom 0.254: 53.44,52.08 38.2,52.08 36.93,53.35 IC24.31 | 53.44,52.08 54.71,50.81 IC21.20 | 89,60.97 90.9,62.88 IC17.29 | 89,60.97 v86.46,60.97 | v53.44,53.35 53.44,52.08 | v94.08,45.73 95.35,47 95.35,54.62 89,60.97
D3  (via drill 0.61)
  Top 0.254: IC22.15 80.11,5.09 81.38,6.36 85.82,6.36 87.09,5.09 97.89,5.09 IC23.15 | v43.28,48.27 52.17,57.16 57.25,57.16 61.06,60.97 82.01,60.97 v82.65,61.61 | v83.92,68.59 86.46,71.13 v87.73,71.13
  Bottom 0.254: IC21.19 54.71,48.27 54.07,48.91 43.91,48.91 v43.28,48.27 42.01,47 39.47,47 36.29,50.18 IC24.30 | IC23.15 100.43,5.09 101.7,6.36 116.94,6.36 118.21,5.09 IC29.15 120.75,5.09 122.65,7 125.19,7 125.19,48.27 123.92,49.54 123.29,49.54 118.21,54.62 113.13,54.62 108.68,59.07 108.05,59.07 108.05,66.69 107.41,67.32 106.14,67.32 105.51,66.69 97.25,66.69 94.71,64.15 IC17.28 94.08,64.78 v87.73,71.13 | v82.65,61.61 82.65,68.59 v83.92,68.59
D4  (via drill 0.61)
  Top 0.254: IC24.29 36.93,48.27 38.2,47 42.01,47 42.64,46.37 54.07,46.37 54.71,45.73 IC21.18 56.61,46.37 61.06,50.81 62.96,50.81 v66.14,53.99 | 96.62,54.62 v96.62,57.16 | v73.12,54.62 96.62,54.62 | 96.62,54.62 v110.59,54.62
  Bottom 0.254: IC22.16 80.11,7.63 81.38,8.9 96.62,8.9 97.89,7.63 IC23.16 100.43,7.63 101.7,8.9 116.94,8.9 118.21,7.63 IC29.16 120.11,8.27 124.56,12.71 124.56,47 122.65,47 118.84,50.81 118.84,52.08 114.4,52.08 111.86,54.62 v110.59,54.62 | v96.62,57.16 96.62,62.24 IC17.27 | v73.12,54.62 72.49,53.99 v66.14,53.99
D5  (via drill 0.61)
  Top 0.254: v97.89,57.8 97.25,58.43 80.74,58.43 v78.2,55.89 | v31.85,43.19 34.39,45.73 IC24.28
  Bottom 0.254: 96.62,11.44 81.38,11.44 80.11,10.17 IC22.17 78.2,9.54 74.39,5.73 74.39,1.92 48.36,1.92 47.72,2.55 47.72,16.52 36.93,16.52 30.58,22.87 19.78,22.87 18.51,24.14 18.51,29.22 21.69,29.22 31.85,39.38 v31.85,43.19 | 96.62,11.44 97.89,10.17 IC23.17 | 96.62,11.44 116.94,11.44 118.21,10.17 IC29.17 | IC24.28 36.93,45.73 38.2,44.46 53.44,44.46 54.71,43.19 IC21.17 56.61,42.56 57.88,42.56 57.88,40.02 59.15,38.75 60.42,38.75 60.42,41.92 62.96,44.46 64.87,44.46 64.87,49.54 66.14,50.81 73.12,50.81 v78.2,55.89 | v97.89,57.8 99.16,57.8 99.16,62.24 IC17.26
D6  (via drill 0.61)
  Top 0.254: IC22.18 80.11,12.71 81.38,13.98 85.19,13.98 86.46,12.71 97.89,12.71 IC23.18 | v42.64,36.84 50.9,36.84 54.71,40.65 IC21.16 57.25,40.65 58.52,41.92 64.23,41.92 64.87,42.56 66.14,42.56 69.31,39.38 74.39,39.38 77.57,42.56 80.11,42.56 80.11,49.54 84.55,53.99 95.98,53.99 v96.62,53.35 | v38.2,38.11 38.2,42.56 36.29,42.56 IC24.27 36.29,43.83 37.56,43.83 37.56,46.37 36.93,47 33.12,47 v33.12,49.54 | v29.94,59.7 26.13,59.7 26.13,44.46 27.4,43.19 27.4,22.24 29.31,20.33 29.31,8.9 36.93,1.28 106.78,1.28 118.21,12.71 IC29.18
  Bottom 0.254: IC29.18 118.21,12.71 116.94,13.98 101.7,13.98 100.43,12.71 IC23.18 | v42.64,36.84 39.47,36.84 v38.2,38.11 | v96.62,53.35 99.79,53.35 99.79,57.8 101.7,59.7 101.7,62.24 IC17.25 | v29.94,59.7 29.94,52.08 30.58,52.08 v33.12,49.54
D7  (via drill 0.61)
  Top 0.254: 118.84,52.08 118.84,48.91 v118.21,48.91 | 118.84,52.08 118.84,53.99 118.21,54.62 113.13,54.62 113.13,57.16 111.86,58.43 109.32,58.43 104.87,62.88 IC17.24 | v64.87,41.29 59.15,41.29 56.61,38.75 IC21.15 | v94.08,52.72 94.71,52.08 118.84,52.08
  Bottom 0.254: IC24.26 36.93,40.65 38.2,39.38 53.44,39.38 54.71,38.11 IC21.15 | IC22.19 80.11,15.25 81.38,13.98 96.62,13.98 97.89,15.25 IC23.19 100.43,15.25 101.7,16.52 116.94,16.52 118.21,15.25 IC29.19 120.11,15.89 123.92,15.89 123.92,38.75 118.21,44.46 v118.21,48.91 | v64.87,41.29 65.5,41.92 69.31,41.92 69.95,42.56 69.95,43.19 70.58,43.19 71.85,44.46 85.19,44.46 87.73,47 87.73,52.72 v94.08,52.72
E  (via drill 0.61)
  Top 0.254: v52.8,34.3 54.07,35.57 54.71,35.57 IC21.14 | IC18.9 123.92,53.99 123.92,55.26 IC18.10 | v58.52,69.86 57.88,69.86 57.88,74.31 54.07,78.12 IC2.3 | v111.86,57.16 111.22,57.8 99.16,57.8 95.98,60.97 91.54,60.97 90.27,62.24 90.27,65.42 80.74,65.42 79.47,64.15 IC17.34 | v69.95,44.46 v69.95,55.26
  Bottom 0.254: v52.8,34.3 39.47,34.3 36.29,37.48 IC24.25 | v58.52,69.86 59.79,71.13 IC2.9 61.69,70.5 64.87,67.32 75.03,67.32 78.2,64.15 IC17.34 78.2,62.88 76.93,61.61 76.3,61.61 v69.95,55.26 | v111.86,57.16 122.02,57.16 123.29,55.89 IC18.10 | v69.95,44.46 66.77,44.46 64.23,41.92 63.6,41.92 63.6,40.65 59.15,36.21 57.88,36.21 57.25,35.57 IC21.14
EP
  Top 0.254: IC28.4 52.17,15.25 57.25,15.25 IC28.13
EP1\
  Bottom 0.254: IC28.7 52.17,7.63 52.8,8.27 53.44,8.27 55.98,10.81 55.98,16.52 57.25,17.79 IC28.14
FIRQ\
  Top 0.254: R8.1 71.22,46.37 71.22,47 IC17.4
GND  (via drill 0.61)
  Top 0.508: IC29.14 102.97,5.09 101.7,3.82 86.46,3.82 85.19,5.09 IC23.14 82.65,5.09 81.38,3.82 74.39,3.82 73.12,5.09 64.87,5.09 IC22.14 62.33,5.09 61.06,3.82 48.36,3.82 | BYP19.2 40.74,26.05 40.74,27.32 R13.1 | IC28.1 51.53,23.51 52.8,24.78 53.44,24.78 BYP28.2 | IC27.7 14.07,5.09 17.88,1.28 23.59,1.28 27.4,5.09 C6.2 28.04,5.73 28.04,7 C4.2 28.04,8.27 28.04,9.54 C5.2 | 48.36,3.82 49.63,5.09 IC28.8 | 48.36,3.82 40.74,3.82 39.47,5.09 IC19.8 | 109.95,71.77 114.4,71.77 COM.G2 118.21,74.31 122.02,78.12 C3.2 | 109.95,71.77 COM.5 109.95,71.77 | IC2.11 62.33,76.21 65.5,76.21 C7.2 66.14,76.85 68.04,78.75 68.68,78.75 70.58,80.66 IC20.15 71.85,81.93 73.12,83.2 82.01,83.2 83.28,81.93 IC20.10 83.92,80.02 85.82,78.12 | C11.2 76.93,68.59 78.2,67.32 85.82,67.32 89.63,71.13 COM.G1 | 85.82,78.12 89.63,74.31 90.27,74.31 COM.G1 | RS-232.2 99.16,67.32 97.89,66.05 95.98,66.05 91.54,70.5 COM.G1 | 109.95,71.77 109.95,78.12 85.82,78.12 | BYP24.2 20.42,78.12 20.42,76.85 IC24.1 19.15,76.21 16.61,76.21 IC25.19 14.7,76.85 14.07,76.85 10.26,80.66 BYP25.2 | JP3.1 9.62,26.05 8.35,27.32 IC26.10 8.35,28.59 13.43,33.67 13.43,48.27 14.07,48.27 IC26.19 14.7,48.91 10.89,52.72 10.26,52.72 BYP26.2 10.26,53.99 8.99,55.26 8.35,55.26 IC25.10 6.45,55.89 5.81,55.89 CORE-IO.10 | BYP18.2 115.03,50.81 115.67,50.81 IC18.7 116.94,50.18 116.94,48.27 JP1.1 | BYP29.2 113.76,40.65 111.86,40.65 111.22,40.02 99.16,40.02 97.25,41.92 BYP23.2 95.98,41.92 95.35,42.56 v90.9,42.56 | 40.74,66.05 40.74,64.15 BYP21.2 | 40.74,66.05 40.74,67.96 QG1.7 | 40.74,66.05 52.8,66.05 BYP2.2 | BYP22.2 73.12,40.65 69.31,40.65 66.77,43.19 64.23,43.19 BYP17.2 62.96,43.19 62.33,43.83 v61.06,43.83
  Top 0.508: IC21.23 57.25,58.43 60.42,61.61 64.23,61.61 65.5,62.88 IC17.39
  Bottom 0.508: BYP19.2 41.37,25.41 42.64,24.14 48.36,24.14 49.63,22.87 IC28.1 | IC19.8 36.93,5.09 28.67,5.09 C6.2 | BYP28.2 54.07,25.41 55.34,24.14 59.79,24.14 60.42,23.51 60.42,13.98 57.25,13.98 56.61,13.35 56.61,5.73 51.53,5.73 IC28.8 | BYP20.2 66.14,74.31 66.14,75.58 C7.2 | 9.62,72.4 10.26,72.4 10.89,73.04 | 9.62,72.4 6.45,72.4 5.18,71.13 JP4.1 | 10.89,73.04 14.07,76.21 IC25.19 | BYP27.2 15.97,25.41 17.88,27.32 17.88,29.22 12.8,29.22 10.26,26.68 JP3.1 | CORE-IO.11 3.27,53.35 5.18,55.26 CORE-IO.10 | 9.62,72.4 9.62,56.53 8.35,56.53 IC25.10 | BYP29.2 114.4,41.29 114.4,46.37 116.3,46.37 JP1.1 | IC21.1 40.74,61.61 40.74,62.88 BYP21.2 | 61.69,51.45 57.88,55.26 57.88,57.8 56.61,57.8 IC21.23 54.71,58.43 50.9,58.43 50.9,61.61 53.44,64.15 53.44,65.42 BYP2.2 | 61.69,51.45 63.6,49.54 IC17.1 63.6,47 63.6,46.37 v61.06,43.83 | v90.9,42.56 90.27,41.92 75.66,41.92 74.39,40.65 BYP22.2 | 10.89,73.04 14.07,69.86 38.83,69.86 40.1,68.59 QG1.7 | 61.69,51.45 71.85,51.45 77.57,57.16 80.11,57.16 80.11,64.78 79.47,65.42 78.84,65.42 76.3,67.96 C11.2 | IC27.7 12.16,4.46 12.16,3.82 10.89,2.55 9.62,2.55 3.91,8.27 3.91,27.95 6.45,27.95 IC26.10
HLT\  (via drill 0.61)
  Top 0.254: v68.68,55.26 63.6,50.18 62.33,50.18 61.06,48.91 R5.1
  Bottom 0.254: v68.68,55.26 68.68,61.61 65.5,61.61 64.23,62.88 IC17.40
IO-E\
  Top 0.254: IC24.23 35.02,32.4 33.75,31.13 33.75,12.08 36.29,12.08 36.93,11.44 39.47,11.44 41.37,9.54 41.37,5.73 45.18,5.73 IC19.9
IO-F\  (via drill 0.61)
  Top 0.254: v32.48,34.94 32.48,12.08 36.93,7.63 IC19.7
  Bottom 0.254: v32.48,34.94 32.48,41.92 38.2,41.92 39.47,40.65 IC21.9
IRQ\  (via drill 0.61)
  Top 0.254: IC24.38 35.02,70.5 35.02,69.23 IC24.37 35.02,67.96 v31.85,64.78 | v59.15,40.02 59.15,38.75 57.25,36.84 54.71,36.84 54.07,36.21 47.09,36.21 41.37,30.49 R7.1 | v59.15,46.37 59.79,47 62.33,47 62.96,46.37 64.23,46.37 64.87,47 64.87,50.18 66.77,50.18 68.04,48.91 IC17.3
  Bottom 0.254: v59.15,40.02 v59.15,46.37 59.15,47.64 57.25,49.54 39.47,49.54 36.93,52.08 31.85,52.08 v31.85,64.78
N$1
  Bottom 0.254: COM.6 100.43,73.04 101.06,72.4 106.14,72.4 106.78,71.77 COM.4
N$2
  Top 0.254: QG1.8 48.36,69.23 52.17,73.04 52.8,73.04 IC2.5
  Bottom 0.254: IC2.1 52.8,83.2 51.53,81.93 51.53,74.31 52.8,74.31 IC2.5
N$3
  Top 0.254: IC2.10 60.42,74.31 59.15,75.58 59.15,81.29 59.79,81.29 IC2.13
N$5
  Top 0.254: IC25.18 16.61,73.67 19.15,73.67 IC24.2
N$6
  Top 0.254: IC18.5 116.3,56.53 116.3,57.8 IC18.4 116.3,59.07 116.3,60.34 IC18.3
N$7  (via drill 0.61)
  Top 0.254: v57.88,81.29 58.52,81.29 58.52,71.13 60.42,69.23 IC2.8
  Bottom 0.254: v57.88,81.29 59.79,83.2 60.42,83.2 IC2.14
N$21
  Top 0.254: R1.1 112.49,68.59 121.38,68.59 C3.1
  Bottom 0.254: IC18.1 118.21,66.05 120.75,68.59 121.38,68.59 C3.1
N$22
  Top 0.254: JP1.2 119.48,48.27 119.48,62.88 117.57,62.88 IC18.2
  Bottom 0.254: R2.1 114.4,65.42 115.67,64.15 116.3,64.15 IC18.2
N$23  (via drill 0.61)
  Top 0.254: v30.58,21.6 30.58,33.03 28.67,34.94 28.67,44.46 27.4,45.73 27.4,48.91 31.21,48.91 34.39,52.08 38.2,52.08 39.47,53.35 IC21.4 40.1,53.99 40.1,55.26 IC21.3
  Bottom 0.254: v30.58,21.6 18.51,21.6 18.51,15.89 13.43,10.81 IC27.5
N$24
  Bottom 0.254: IC26.18 15.97,46.37 18.51,48.91 18.51,53.35 19.15,53.35 IC24.10
N$25
  Top 0.254: IC26.17 15.97,43.83 18.51,46.37 18.51,50.81 19.15,50.81 IC24.11
N$27
  Top 0.254: IC27.2 11.53,17.79 10.89,17.79 R11.A | IC27.6 11.53,7.63 9.62,9.54 8.35,9.54 R11.S
  Bottom 0.254: C6.1 22.96,5.73 22.32,6.36 15.34,6.36 14.07,7.63 IC27.6 | R11.A 10.26,16.52 7.72,13.98 7.72,11.44 R11.S
N$28
  Top 0.254: R9.1 22.32,2.55 21.05,2.55 R10.2 20.42,3.19 19.78,3.19 14.07,8.9 11.53,8.9 10.89,9.54 10.89,13.35 11.53,13.98 14.7,13.98 14.7,18.43 13.43,19.7 IC27.1
N$94
  Bottom 0.254: IC26.16 15.97,41.29 17.24,42.56 17.24,46.37 19.15,48.27 IC24.12
N$124
  Bottom 0.254: IC26.15 15.97,38.75 17.88,40.65 17.88,45.73 19.15,45.73 IC24.13
N$125
  Bottom 0.254: IC26.14 15.97,36.21 18.51,38.75 18.51,43.19 19.15,43.19 IC24.14
N$126
  Top 0.254: IC26.13 15.97,33.67 17.88,35.57 17.88,40.65 19.15,40.65 IC24.15
N$127
  Top 0.254: IC26.12 15.97,31.13 17.24,32.4 17.24,33.67 18.51,34.94 18.51,38.11 19.15,38.11 IC24.16
N$128
  Top 0.254: IC26.11 15.97,28.59 17.88,30.49 17.88,33.03 19.78,34.94 IC24.17
N$129
  Top 0.254: IC25.17 16.61,71.13 19.15,71.13 IC24.3
N$130
  Top 0.254: IC25.16 16.61,68.59 19.15,68.59 IC24.4
N$131
  Top 0.254: IC25.15 16.61,66.05 19.15,66.05 IC24.5
N$132
  Top 0.254: IC25.14 16.61,63.51 19.15,63.51 IC24.6
N$133
  Top 0.254: IC25.13 16.61,60.97 19.15,60.97 IC24.7
N$134
  Top 0.254: IC25.12 16.61,58.43 19.15,58.43 IC24.8
N$135
  Top 0.254: IC25.11 16.61,55.89 19.15,55.89 IC24.9
N$136
  Bottom 0.254: IC26.1 8.35,50.18 13.43,45.1 13.43,31.76 17.88,31.76 19.15,30.49 IC24.19
N$137
  Bottom 0.254: IC25.1 8.99,78.75 10.26,80.02 16.61,80.02 18.51,78.12 18.51,74.94 33.12,74.94 34.39,73.67 IC24.39
N$138  (via drill 0.61)
  Top 0.254: v26.13,41.29 26.77,41.29 26.77,9.54 23.59,6.36 21.69,6.36 21.05,7 IC27.9 | v26.13,63.51 26.13,76.21 34.39,76.21 IC24.40
  Bottom 0.254: v26.13,41.29 v26.13,63.51
N$140
  Top 0.254: C4.1 23.59,7.63 25.5,9.54 R4.1 25.5,10.81 24.86,10.81 21.05,14.62 IC27.12
  Bottom 0.254: IC27.8 21.05,4.46 21.69,3.82 23.59,3.82 24.23,4.46 24.23,7 22.96,7 C4.1
N$141
  Top 0.254: IC27.13 21.69,17.79 22.32,17.79 R3.1 23.59,17.79 24.86,17.79 R4.2
N$142
  Bottom 0.254: IC27.11 21.69,12.71 24.23,15.25 27.4,15.25 C5.1
N$143
  Top 0.254: R10.1 12.16,2.55 10.89,3.82 10.26,3.82 R11.E
N$145
  Top 0.254: COM.7 103.6,73.67 104.87,73.67 COM.8
N$147  (via drill 0.61)
  Top 0.254: v48.36,58.43 41.37,51.45 IC21.5 | v108.68,67.32 110.59,65.42 113.13,65.42 113.76,64.78 122.02,64.78 123.29,63.51 IC18.13 123.92,62.88 123.92,61.61 IC18.12
  Bottom 0.254: v48.36,58.43 47.72,59.07 43.91,59.07 42.64,60.34 42.64,76.85 44.55,76.85 51.53,83.83 51.53,85.1 99.16,85.1 111.22,73.04 111.22,69.86 v108.68,67.32
N$148
  Top 0.254: LED1.K 123.29,48.91 122.02,50.18 122.02,58.43 123.29,58.43 IC18.11
N$149
  Top 0.254: R12.1 122.02,43.83 123.29,45.1 LED1.A
N$150  (via drill 0.61)
  Top 0.254: R13.2 48.99,27.95 49.63,27.95 JP2.1 | v30.58,50.81 34.39,54.62 36.93,54.62 39.47,57.16 42.01,57.16 45.82,60.97 54.71,60.97 IC21.24
  Bottom 0.254: v30.58,50.81 30.58,44.46 36.93,44.46 39.47,41.92 52.17,41.92 54.71,39.38 57.25,39.38 57.88,38.75 57.88,36.84 54.71,36.84 54.07,36.21 54.07,34.3 57.25,34.3 57.88,33.67 57.88,28.59 51.53,28.59 JP2.1
N$151  (via drill 0.61)
  Top 0.254: v73.12,3.19 107.41,3.19 118.21,13.98 120.75,13.98 124.56,17.79 124.56,50.18 IC18.8
  Bottom 0.254: v73.12,3.19 72.49,2.55 48.99,2.55 48.99,8.27 49.63,8.9 52.8,8.9 52.8,14.62 57.88,19.7 IC28.15
N$153
  Top 0.254: IC20.7 84.55,73.04 85.82,73.04 IC20.8
N$154  (via drill 0.61)
  Top 0.254: v83.28,83.83 81.38,85.74 47.09,85.74 43.91,82.56 9.62,82.56 8.99,81.93 1.37,81.93 1.37,23.51 8.99,15.89 10.89,15.89 11.53,15.25 IC27.3
  Bottom 0.254: v83.28,83.83 68.04,83.83 66.14,81.93 C7.1
N$155
  Bottom 0.254: C9.2 80.74,71.13 79.47,72.4 78.84,72.4 IC20.5
N$156
  Top 0.254: C9.1 76.3,71.77 76.3,72.4 IC20.4
N$157
  Top 0.254: C8.2 73.76,69.23 75.03,70.5 75.03,72.4 73.76,72.4 IC20.3
N$158
  Top 0.254: C8.1 68.68,69.23 69.95,70.5 69.95,72.4 68.68,72.4 IC20.1
N$159
  Top 0.254: C11.1 81.38,69.23 80.11,70.5 80.11,73.04 80.74,73.04 IC20.6
N$160
  Top 0.254: C10.2 73.12,71.13 71.85,72.4 71.22,72.4 IC20.2
NMI\  (via drill 0.61)
  Top 0.254: v50.26,47.64 54.71,52.08 62.96,52.08 67.41,56.53 69.95,56.53 v75.66,50.81 | R6.1 68.04,45.73 66.77,47 66.14,47 IC17.2
  Bottom 0.254: v50.26,47.64 43.91,47.64 42.01,45.73 IC21.7 | v75.66,50.81 75.03,50.18 68.04,50.18 66.77,48.91 IC17.2
PIA-A0
  Top 0.254: IC25.2 6.45,76.21 5.18,74.94 2.64,74.94 2,74.31 2,66.69 2.64,66.69 CORE-IO.1
PIA-A1
  Top 0.254: IC25.3 7.08,73.04 5.81,71.77 5.81,66.69 5.18,66.69 CORE-IO.2
PIA-A2
  Bottom 0.254: IC25.4 7.08,70.5 3.91,67.32 3.91,65.42 2.64,64.15 CORE-IO.3
PIA-A3
  Top 0.254: IC25.5 8.35,67.96 9.62,66.69 9.62,64.78 5.81,64.78 5.18,64.15 CORE-IO.4
PIA-A4
  Bottom 0.254: IC25.6 7.08,65.42 6.45,64.78 4.54,64.78 3.91,64.15 3.91,61.61 2.64,61.61 CORE-IO.5
PIA-A5
  Top 0.254: IC25.7 7.08,62.88 5.81,61.61 5.18,61.61 CORE-IO.6
PIA-A6
  Top 0.254: IC25.8 7.08,60.34 6.45,59.7 4.54,59.7 3.27,58.43 CORE-IO.7
PIA-A7
  Top 0.254: IC25.9 6.45,58.43 5.81,58.43 CORE-IO.8
PIA-B0
  Bottom 0.254: IC26.2 7.08,48.91 6.45,49.54 4.54,49.54 3.27,50.81 CORE-IO.13
PIA-B1
  Top 0.254: IC26.3 8.35,46.37 9.62,47.64 9.62,49.54 5.81,49.54 5.18,50.18 CORE-IO.14
PIA-B2
  Top 0.254: IC26.4 7.08,43.83 6.45,44.46 4.54,44.46 3.91,45.1 3.91,47.64 2.64,47.64 CORE-IO.15
PIA-B3
  Bottom 0.254: IC26.5 8.35,41.29 9.62,42.56 9.62,47 5.81,47 5.18,47.64 CORE-IO.16
PIA-B4
  Top 0.254: IC26.6 7.08,38.75 3.91,41.92 3.91,43.83 2.64,45.1 CORE-IO.17
PIA-B5
  Bottom 0.254: IC26.7 7.08,36.21 3.91,39.38 3.91,45.73 4.54,45.73 CORE-IO.18
PIA-B6
  Top 0.254: IC26.8 7.08,33.67 2.64,38.11 2.64,42.56 CORE-IO.19
PIA-B7
  Top 0.254: IC26.9 8.35,31.13 9.62,32.4 9.62,41.92 5.81,41.92 5.18,42.56 CORE-IO.20
Q  (via drill 0.61)
  Top 0.254: v60.42,66.69 58.52,68.59 54.71,68.59 IC2.7
  Bottom 0.254: IC2.7 54.07,69.23 55.98,71.13 55.98,78.75 59.79,78.75 IC2.12 | v60.42,66.69 73.12,66.69 75.66,64.15 IC17.35
R/W\  (via drill 0.61)
  Top 0.254: IC24.21 36.93,27.95 38.2,29.22 43.28,29.22 47.09,33.03 54.71,33.03 IC21.13 57.25,33.03 61.06,36.84 64.87,36.84 66.14,35.57 77.57,35.57 IC22.27 | v83.28,50.81 83.28,50.18 82.65,49.54 v82.65,40.02
  Bottom 0.254: v83.28,50.81 83.92,50.81 83.92,62.24 IC17.32 | v82.65,40.02 80.74,38.11 80.74,36.21 79.47,36.21 IC22.27
RST\  (via drill 0.61)
  Top 0.254: IC24.34 36.93,60.97 38.2,62.24 59.79,62.24 62.96,65.42 69.31,65.42 70.58,64.15 IC17.37 71.85,64.15 73.76,66.05 92.81,66.05 92.81,62.24 93.44,61.61 99.79,61.61 v102.33,59.07 | v108.05,53.35 115.67,53.35 IC18.6
  Bottom 0.254: v102.33,59.07 v108.05,53.35
RX  (via drill 0.61)
  Top 0.254: v44.55,60.97 42.01,58.43 IC21.2 | v68.68,77.48 70.58,79.39 76.93,79.39 78.2,80.66 IC20.12
  Bottom 0.254: v44.55,60.97 45.82,62.24 47.72,62.24 52.8,67.32 54.71,67.32 56.61,69.23 56.61,77.48 v68.68,77.48
RXD  (via drill 0.61)
  Top 0.254: v92.17,76.85 96.62,72.4 | 96.62,72.4 96.62,69.86 RS-232.3 | 96.62,72.4 102.33,72.4 103.6,71.13 COM.3
  Bottom 0.254: v92.17,76.85 80.74,76.85 76.93,80.66 IC20.13
TX  (via drill 0.61)
  Top 0.254: v52.17,59.7 41.37,48.91 IC21.6 | v62.96,72.4 65.5,74.94 67.41,74.94 69.95,77.48 77.57,77.48 80.74,80.66 IC20.11
  Bottom 0.254: v52.17,59.7 52.17,61.61 57.25,66.69 57.25,72.4 v62.96,72.4
TXD
  Top 0.254: RS-232.1 101.7,69.86 101.7,70.5 COM.2
  Bottom 0.254: IC20.14 74.39,80.66 79.47,75.58 95.98,75.58 99.16,72.4 99.79,72.4 100.43,71.77 101.06,71.77 COM.2
VCC  (via drill 0.61)
  Top 0.508: BYP26.1 15.34,52.72 15.34,51.45 IC26.20 16.61,50.81 17.88,52.08 21.69,52.08 22.32,51.45 22.32,28.59 21.05,28.59 IC24.20 20.42,27.32 20.42,26.05 BYP27.1 20.42,24.78 20.42,22.87 | CORE-IO.9 2.64,55.26 4.54,53.35 CORE-IO.12 | IC25.20 15.34,79.39 15.34,80.66 BYP25.1 15.97,81.29 22.32,81.29 24.86,78.75 BYP24.1 | BYP18.1 114.4,56.53 114.4,61.61 108.68,61.61 108.05,62.24 108.05,65.42 106.78,65.42 R2.2 106.14,66.05 104.24,67.96 R1.2 104.87,68.59 109.32,68.59 110.59,67.32 122.02,67.32 123.29,66.05 IC18.14 | 50.26,82.56 51.53,81.29 52.17,81.29 IC2.2 | 50.26,82.56 48.99,83.83 QG1.14 | 50.26,82.56 67.41,82.56 68.04,81.93 IC20.16 | C10.1 68.68,70.5 66.77,68.59 BYP20.1 65.5,68.59 62.96,66.05 61.69,66.05 61.06,65.42 58.52,65.42 BYP2.1 57.88,66.05 55.34,63.51 46.45,63.51 BYP21.1 | IC2.4 54.07,75.58 55.34,74.31 55.34,71.77 54.07,71.77 IC2.6 | 20.42,22.87 20.42,20.97 IC27.14 19.78,19.7 18.51,18.43 18.51,10.17 | 20.42,22.87 5.81,22.87 R14.2 | R3.2 22.32,10.17 21.69,10.17 IC27.10 19.15,10.17 18.51,10.17 | 18.51,10.17 16.61,10.17 14.07,12.71 IC27.4 | IC29.28 119.48,38.75 119.48,40.02 BYP29.1 | R12.2 122.02,36.21 120.75,37.48 120.11,37.48 IC29.28 | BYP22.1 78.84,40.02 78.84,38.75 IC22.28 80.11,38.11 82.65,38.11 IC23.1 | IC23.27 98.52,36.21 98.52,37.48 IC23.28 | IC23.28 100.43,38.11 102.97,38.11 IC29.1 105.51,38.11 118.21,38.11 IC29.28 | IC23.1 85.19,38.11 97.89,38.11 IC23.28 | IC17.7 78.84,47 78.84,46.37 R8.2 78.2,45.73 75.66,43.19 69.31,43.19 BYP17.1 68.04,43.19 65.5,45.73 61.69,45.73 R6.2 60.42,45.73 59.15,44.46 43.28,44.46 42.01,43.19 IC21.8 41.37,42.56 42.64,41.29 42.64,38.75 41.37,38.75 IC21.10 40.1,37.48 38.2,35.57 36.93,35.57 IC24.24
  Top 0.508: IC24.22 36.93,30.49 39.47,33.03 IC21.12 | IC28.16 58.52,23.51 58.52,24.78 BYP28.1 | IC19.16 45.82,23.51 45.82,24.78 BYP19.1 45.82,26.05 45.82,30.49 47.72,30.49 R7.2 48.99,30.49 49.63,30.49 JP2.2 | v83.92,45.73 83.92,38.75 IC23.1
  Bottom 0.508: IC26.20 14.07,50.81 12.8,52.08 7.08,52.08 5.81,53.35 CORE-IO.12 | IC25.20 14.07,78.75 12.8,77.48 4.54,77.48 4.54,74.31 JP4.2 2.64,73.67 1.37,73.67 1.37,57.8 2.64,56.53 CORE-IO.9 | BYP21.1 45.82,64.15 52.17,70.5 52.8,70.5 IC2.6 | R5.2 61.06,56.53 61.06,65.42 58.52,65.42 BYP2.1 | IC2.2 54.07,80.66 55.34,79.39 55.34,76.85 54.07,76.85 IC2.4 | 48.99,85.1 48.36,84.47 QG1.14 | 48.99,85.1 50.26,86.37 100.43,86.37 104.87,81.93 123.92,81.93 123.92,66.69 IC18.14 | 48.99,85.1 32.48,85.1 26.13,78.75 BYP24.1 | R9.2 29.94,2.55 28.67,3.82 27.4,3.82 24.86,6.36 24.86,8.9 23.59,10.17 R3.2 | BYP23.1 101.7,41.29 99.16,38.75 IC23.28 | IC24.24 36.93,35.57 39.47,33.03 IC21.12 42.01,33.03 44.55,30.49 47.72,30.49 R7.2 | IC28.16 57.25,22.87 53.44,22.87 50.9,25.41 46.45,25.41 BYP19.1 | v83.92,45.73 79.47,45.73 R8.2 | BYP27.1 21.05,25.41 22.32,24.14 35.66,24.14 37.56,26.05 37.56,29.86 36.29,29.86 IC24.22

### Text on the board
Top: Component Side
Bottom: PA8PDP/VRS | Solder side
tPlace: + | RealConsole CORE - Rev.1
tValues: + | -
